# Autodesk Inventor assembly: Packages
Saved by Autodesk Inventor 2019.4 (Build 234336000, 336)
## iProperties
Created: 2021-03
Part Number: Packages
Document SubType Name: Assembly
Designer: Administrator
Title: Packages
Author: Administrator
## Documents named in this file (1)
- c:\worker\convert-fusion-r02\tmp\job-1\102\output\files\0328255d-0a6c-475c-bcc0-a427a23ae33c\Packages.iam
